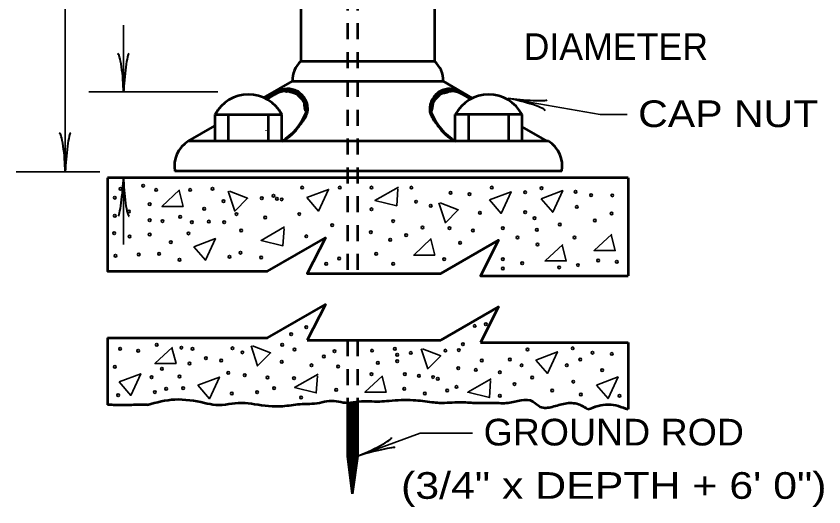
# Model space of a CAD drawing. Extents: x -608 to 72, y 36 to 476.
# Drawn here: x -462.2 to -401.7, y 238.4 to 275.1 of the extents above; entities that cross this region are included whole.
import ezdxf
from ezdxf.enums import TextEntityAlignment as Align

# ---------------------------------------------------------------- set-up
doc = ezdxf.new("R2010")
doc.units = 0
doc.header["$LTSCALE"] = 0.8
doc.linetypes.add('SHORT_DASHED', pattern=[2.7, 1.5, -1.2])
doc.layers.add('1', color=7, linetype='Continuous', lineweight=53)

msp = doc.modelspace()

# ---------------------------------------------------------------- linework, layer by layer
at = {"layer": '1'}
for p, q in [((-430.8494, 389.7532), (-430.8494, 271.7708)), ((-440.8494, 280.6042), (-440.8494, 271.7708)), ((-440.8494, 271.7708), (-430.8494, 271.7708)), ((-443.6563, 269.0234), (-441.4957, 270.2708)), ((-441.4957, 270.2708), (-430.2031, 270.2708)), ((-428.0152, 269.0077), (-430.2031, 270.2708)), ((-443.5354, 268.9779), (-442.696, 269.4626)), ((-443.4408, 268.9778), (-442.6493, 269.4348)), ((-443.4304, 268.9597), (-442.6389, 269.4167)), ((-443.415, 268.9331), (-442.6235, 269.3901)), ((-428.138, 268.9331), (-428.9295, 269.3901)), ((-428.1226, 268.9597), (-428.9141, 269.4167)), ((-428.1122, 268.9778), (-428.9037, 269.4348)), ((-428.0176, 268.9779), (-428.857, 269.4626)), ((-447.29, 265.7708), (-447.29, 267.7708)), ((-447.29, 267.7708), (-442.29, 267.7708)), ((-446.29, 265.7708), (-446.29, 267.7708)), ((-443.29, 265.7708), (-443.29, 267.7708)), ((-442.29, 265.7708), (-442.29, 267.7708)), ((-429.288, 265.7708), (-429.288, 267.7708)), ((-424.288, 267.7708), (-429.288, 267.7708)), ((-428.288, 265.7708), (-428.288, 267.7708)), ((-425.288, 265.7708), (-425.288, 267.7708)), ((-424.288, 265.7708), (-424.288, 267.7708)), ((-449.29, 265.7708), (-447.3094, 266.9143)), ((-422.4088, 265.7708), (-424.2792, 266.8507)), ((-422.3122, 265.7708), (-449.29, 265.7708)), ((-421.3122, 263.5208), (-450.29, 263.5208)), ((-416.3494, 263.0208), (-455.3494, 263.0208)), ((-416.3494, 263.0208), (-416.3494, 255.6748)), ((-455.3494, 251.0208), (-443.3494, 251.0208)), ((-455.3494, 251.0208), (-455.3494, 246.0208)), ((-440.3812, 250.8478), (-430.3812, 250.8478)), ((-427.4131, 250.6748), (-416.3494, 250.6748)), ((-416.3494, 250.6748), (-416.3494, 245.6748)), ((-437.3739, 246.1689), (-437.3739, 242.1689)), ((-437.3382, 246.1689), (-437.3382, 241.8903)), ((-437.3007, 246.1689), (-437.3007, 241.5968)), ((-437.2631, 246.1689), (-437.2631, 241.3033)), ((-437.2255, 246.1689), (-437.2255, 241.0098)), ((-437.1879, 246.1689), (-437.1879, 240.7163)), ((-437.1628, 246.1689), (-437.1628, 240.5204)), ((-437.1252, 246.1689), (-437.1252, 240.2269)), ((-437.1002, 246.1689), (-437.1002, 240.031)), ((-437.0626, 246.1689), (-437.0626, 239.7375)), ((-437.025, 246.1689), (-437.025, 239.444)), ((-436.9999, 246.1689), (-436.9999, 239.4366)), ((-436.9748, 246.1689), (-436.9748, 239.6188)), ((-436.9373, 246.1689), (-436.9373, 239.892)), ((-436.9122, 246.1689), (-436.9122, 240.0742)), ((-436.8746, 246.1689), (-436.8746, 240.3473)), ((-436.8245, 246.1689), (-436.8245, 240.7113)), ((-436.7869, 246.1689), (-436.7869, 240.9844)), ((-436.7618, 246.1689), (-436.7618, 241.1667)), ((-436.7117, 246.1689), (-436.7117, 241.5312)), ((-436.6867, 246.1689), (-436.6867, 241.7129)), ((-436.6239, 246.2541), (-436.6239, 242.1689)), ((-437.3739, 242.1689), (-437.0124, 239.3457)), ((-436.6239, 242.1689), (-437.0124, 239.3457))]:
    msp.add_line(p, q, dxfattribs=at)
at = {"layer": '1', "lineweight": 35}
for p, q in [((-458.5165, 324.3555), (-458.5165, 263.5208)), ((-454.1446, 269.4623), (-454.1446, 274.4623)), ((-447.0688, 269.4623), (-456.7412, 269.4623)), ((-455.9253, 263.4647), (-462.1882, 263.4647)), ((-454.1446, 263.0208), (-454.1446, 258.0208))]:
    msp.add_line(p, q, dxfattribs=at)
at = {"layer": '1', "linetype": 'SHORT_DASHED'}
for p, q in [((-437.3739, 276.7708), (-437.3739, 255.8478)), ((-436.6239, 276.7708), (-436.6239, 255.8478)), ((-437.3739, 250.8478), (-437.3739, 246.1689)), ((-436.6239, 250.8478), (-436.6239, 246.2541))]:
    msp.add_line(p, q, dxfattribs=at)
at = {"layer": '1', "linetype": 'SHORT_DASHED', "lineweight": 13}
for p, q in [((-437.3739, 255.8478), (-437.3739, 255.8234)), ((-436.6239, 255.8478), (-436.6239, 255.8234))]:
    msp.add_line(p, q, dxfattribs=at)
at = {"layer": '1', "lineweight": 13}
for p, q in [((-437.3739, 242.1689), (-436.6239, 242.1689)), ((-437.0124, 242.3457), (-437.0124, 239.3457)), ((-436.9989, 242.1689), (-436.9989, 242.5212))]:
    msp.add_line(p, q, dxfattribs=at)
at = {"layer": '1', "lineweight": 35}
for points in [[(-425.3201, 268.9852), (-418.4264, 267.7697), (-416.4264, 267.7697)], [(-449.9446, 262.1177), (-451.2632, 260.8869), (-449.6808, 260.8869), (-449.9885, 262.0737)], [(-446.2964, 262.0297), (-445.8129, 260.5353), (-444.8459, 261.5023), (-446.2085, 262.0297)], [(-433.5497, 262.3374), (-435.3078, 261.3265), (-433.6815, 260.9309), (-433.5936, 262.2056)], [(-430.5168, 261.1507), (-430.0333, 259.6562), (-429.0663, 260.6232), (-430.4289, 261.1507)], [(-442.0768, 259.3486), (-443.8349, 258.3377), (-442.2086, 257.9421), (-442.1207, 259.2167)], [(-431.0882, 258.4695), (-432.4068, 257.2387), (-430.8245, 257.2387), (-431.1322, 258.4255)], [(-417.5687, 258.8034), (-418.8872, 257.5727), (-417.3049, 257.5727), (-417.6126, 258.7594)], [(-421.2426, 258.0299), (-422.5612, 256.7992), (-420.9788, 256.7992), (-421.2865, 257.9859)], [(-450.472, 250.338), (-451.7906, 249.1072), (-450.2082, 249.1072), (-450.5159, 250.294)], [(-444.5821, 250.4258), (-444.0986, 248.9314), (-443.1316, 249.8984), (-444.4942, 250.4258)], [(-431.8354, 250.2061), (-431.3519, 248.7117), (-430.3849, 249.6787), (-431.7475, 250.2061)], [(-439.5714, 248.3161), (-441.3296, 247.3052), (-439.7032, 246.9096), (-439.6153, 248.1842)], [(-434.7365, 248.1842), (-436.0551, 246.9535), (-434.4727, 246.9535), (-434.7804, 248.1402)], [(-426.605, 247.9644), (-428.3632, 246.9535), (-426.7368, 246.5579), (-426.6489, 247.8326)], [(-436.6239, 242.1689), (-431.9254, 243.879), (-428.0115, 243.879)]]:
    msp.add_lwpolyline(points, dxfattribs=at)
at = {"layer": '1'}
for points in [[(-455.3494, 263.0208), (-455.3494, 256.0208), (-443.3494, 256.0208), (-439.0192, 258.5208), (-440.3812, 255.8478), (-430.3812, 255.8478), (-426.0511, 258.3478), (-427.4131, 255.6748), (-416.3494, 255.6748)], [(-430.3812, 255.8478), (-426.0511, 258.3478), (-427.4131, 255.6748)], [(-443.3494, 251.0208), (-439.0192, 253.5208), (-440.3812, 250.8478)], [(-430.3812, 250.8478), (-426.0511, 253.3478), (-427.4131, 250.6748)]]:
    msp.add_lwpolyline(points, dxfattribs=at)
at = {"layer": '1', "lineweight": 35}
for points in [[(-440.4065, 261.5462), (-439.5274, 260.5353), (-438.7802, 262.1617)], [(-422.8688, 261.4582), (-421.9897, 260.4473), (-421.2425, 262.0737)], [(-426.7368, 261.3705), (-425.8578, 260.3596), (-425.1105, 261.9859)], [(-448.8897, 257.8541), (-448.0106, 256.8432), (-447.2633, 258.4695)], [(-423.2645, 249.3709), (-422.3854, 248.36), (-421.6382, 249.9863)], [(-454.4796, 247.7226), (-453.6005, 246.7117), (-452.8533, 248.338)], [(-448.582, 247.4809), (-447.7029, 246.47), (-446.9557, 248.0963)], [(-418.7205, 247.4856), (-417.8414, 246.4747), (-417.0942, 248.101)]]:
    msp.add_lwpolyline(points, close=True, dxfattribs=at)
for centre in [(-454.3646, 262.1966), (-452.6727, 262.4382), (-451.7027, 262.1177), (-449.1533, 262.1177), (-447.4831, 262.2056), (-440.7582, 262.2934), (-437.9451, 262.2934), (-435.5716, 262.2934), (-432.5827, 262.2934), (-429.6377, 261.8978), (-426.561, 262.2934), (-424.0557, 261.9418), (-422.8249, 262.2495), (-420.2756, 261.9857), (-454.7965, 261.5375), (-443.791, 261.5023), (-442.9119, 261.6781), (-442.6482, 261.4583), (-442.2966, 261.4143), (-428.2312, 261.81), (-419.121, 261.7309), (-417.5289, 261.7132), (-452.1861, 261.0542), (-448.0985, 260.7111), (-446.648, 261.2825), (-432.2311, 261.2386), (-431.1322, 260.9309), (-420.1877, 260.843), (-454.7965, 260.184), (-453.7362, 260.5047), (-449.9006, 260.0958), (-445.681, 260.3155), (-440.9779, 260.3155), (-435.5716, 260.6672), (-427.4401, 260.4034), (-424.0557, 260.4474), (-417.5772, 260.3596), (-452.1861, 259.8456), (-451.2192, 259.7881), (-449.0215, 259.7002), (-447.7468, 259.7441), (-446.604, 259.7002), (-443.5272, 260.0518), (-438.5165, 259.4804), (-433.9452, 259.7881), (-423.3523, 260.0078), (-421.4623, 259.5243), (-418.8341, 259.8278), (-454.8448, 258.8788), (-445.3293, 259.0848), (-435.6155, 258.9529), (-431.7476, 259.3046), (-429.7257, 259.2607), (-427.9675, 259.0848), (-425.7259, 259.2607), (-423.1766, 259.1287), (-453.6847, 258.6371), (-452.1861, 258.7821), (-449.2852, 258.8651), (-440.4505, 258.6452), (-434.1651, 258.3816), (-432.9783, 258.7332), (-424.627, 258.5573), (-420.3635, 258.5573), (-450.6038, 258.2057), (-428.9345, 258.1617), (-423.1326, 258.0299), (-454.7482, 257.1868), (-453.0079, 257.2836), (-451.4829, 257.3267), (-446.2084, 257.1069), (-445.3733, 257.4146), (-443.8349, 257.0629), (-435.2199, 257.3267), (-449.9446, 256.8871), (-438.956, 256.5794), (-437.9891, 256.975), (-433.9452, 256.5794), (-430.1212, 256.9311), (-425.7259, 256.9311), (-424.2754, 256.6234), (-420.0997, 256.4915), (-418.5924, 256.8307), (-417.1905, 256.7341), (-425.7259, 256.2278), (-421.5063, 256.3157), (-440.4505, 251.8324), (-427.8357, 251.9203), (-427.0006, 252.0522), (-441.5933, 251.3049), (-451.6587, 250.5137), (-442.2526, 250.5137), (-428.7147, 250.5577), (-454.4052, 250.2103), (-453.0517, 250.0652), (-449.8127, 250.294), (-448.9776, 250.2061), (-445.9887, 250.2501), (-445.2415, 249.9424), (-441.3296, 250.1622), (-438.3407, 250.0302), (-435.5277, 250.0742), (-433.8134, 250.2061), (-432.6267, 249.8984), (-430.0334, 250.0742), (-429.0224, 250.1182), (-423.8798, 250.1622), (-420.4953, 250.2501), (-419.0198, 249.9202), (-417.5696, 249.8236), (-447.9666, 249.5028), (-446.8238, 249.327), (-442.2966, 249.2391), (-439.1318, 249.6347), (-433.6376, 249.7666), (-433.6376, 249.2831), (-427.3082, 249.327), (-425.1984, 249.4149), (-419.9239, 249.4149), (-454.792, 248.8568), (-451.2632, 248.7117), (-449.1973, 249.1072), (-440.0549, 248.9754), (-438.077, 248.8875), (-435.0881, 249.1512), (-429.0664, 248.7556), (-427.7477, 248.6238), (-424.3193, 248.9754), (-420.9349, 248.9754), (-418.2947, 248.615), (-452.0366, 248.0832), (-449.9446, 248.1402), (-446.2963, 248.404), (-445.0657, 248.2282), (-443.3514, 248.0523), (-441.3735, 248.0084), (-435.5716, 248.3161), (-433.0662, 248.3161), (-432.0113, 248.1842), (-430.9564, 248.0963), (-425.9457, 248.4479), (-423.5282, 248.0523), (-430.6047, 247.9644), (-424.8468, 247.5688), (-420.4514, 247.7447), (-451.7949, 246.9714), (-450.9555, 247.2172), (-449.6808, 247.2612), (-446.0327, 246.8656), (-444.1426, 246.9535), (-442.8679, 247.2612), (-438.2088, 247.1293), (-433.1102, 247.2172), (-431.5718, 246.8656), (-429.9015, 247.0853), (-429.1982, 247.3491), (-422.0337, 247.0853), (-419.88, 246.7777), (-454.5503, 246.7297), (-440.8461, 246.5579), (-425.9457, 246.6898), (-416.9895, 246.6814)]:
    msp.add_circle(centre, 0.1, dxfattribs=at)
at = {"layer": '1'}
for centre, radius, start, end in [((-439.6024, 270.3443), 1.8947, 131.15753, 182.22112), ((-432.0964, 270.3443), 1.8947, 357.77888, 48.84247), ((-444.79, 266.4375), 2.8333, 28.07249, 151.92751), ((-441.9941, 267.9914), 1.5294, 357.56619, 122.5437), ((-441.8732, 268.1733), 1.5294, 357.56619, 122.5437), ((-441.8732, 268.1733), 1.5294, 357.56619, 122.5437), ((-429.6798, 268.1733), 1.5294, 57.4563, 182.43381), ((-429.6798, 268.1733), 1.5294, 57.4563, 182.43381), ((-429.5589, 267.9914), 1.5294, 57.4563, 182.43381), ((-426.788, 266.4375), 2.8333, 28.07249, 151.92751), ((-442.0355, 268.3486), 1.7074, 321.26362, 351.91119), ((-429.5175, 268.3486), 1.7074, 188.08881, 218.73638), ((-444.4981, 269.4887), 4.3242, 300.70688, 338.8212), ((-427.0549, 269.4887), 4.3242, 201.1788, 239.29312), ((-443.7041, 268.7229), 3.2733, 295.59515, 327.88518), ((-475.2243, 293.4906), 43.3434, 322.29634, 322.79175), ((-396.3287, 293.4906), 43.3434, 217.20825, 217.70366), ((-427.8489, 268.7229), 3.2733, 212.11482, 244.40485), ((-445.4058, 267.8783), 2.3574, 326.68295, 327.02077), ((-448.1767, 263.9288), 2.1523, 121.14818, 190.92684), ((-423.4255, 263.9288), 2.1523, 349.07316, 58.85182)]:
    msp.add_arc(centre, radius, start, end, dxfattribs=at)
at = {"layer": '1', "lineweight": 40}
for centre, major_axis, ratio, start_param, end_param in [((-454.4209, 270.5535), (0.1562, -1.7857), 0.122415, 0.8963533, 3.1415927), ((-453.933, 270.5828), (0.1757, 1.7565), 0.07063, 6.2823074, 8.5597026), ((-424.2934, 268.5236), (-1.7315, 0.4639), 0.122415, 3.1415927, 5.386832), ((-424.1799, 268.999), (1.7603, -0.132), 0.07063, 4.006668, 6.2840632), ((-458.7928, 264.612), (0.1562, -1.7857), 0.122415, 0.8963533, 3.1415927), ((-458.3049, 264.6413), (0.1757, 1.7565), 0.07063, 6.2823074, 8.5597026), ((-454.3562, 261.9003), (-0.1757, -1.7565), 0.07063, 6.2823074, 8.5597026), ((-453.8683, 261.9296), (-0.1562, 1.7857), 0.122415, 0.8963533, 3.1415927), ((-435.693, 242.8018), (-1.6246, -0.7575), 0.122415, 0.8963533, 3.1415927), ((-435.4986, 242.3533), (1.7106, 0.4357), 0.07063, 6.2823074, 8.5597026)]:
    msp.add_ellipse(centre, major_axis=major_axis, ratio=ratio, start_param=start_param, end_param=end_param, dxfattribs=at)
at = {"layer": '1'}
for points in [[(-441.584, 266.2357), (-441.4752, 266.3445), (-441.439, 266.3928), (-441.3665, 266.4895), (-441.3061, 266.5379), (-441.2093, 266.6467), (-441.1489, 266.7192), (-440.9918, 266.9125), (-440.8952, 267.0576), (-440.8105, 267.1542), (-440.7501, 267.2267), (-440.7259, 267.2751), (-440.6534, 267.3476), (-440.6413, 267.396), (-440.6172, 267.4443), (-440.593, 267.4927), (-440.5688, 267.5652), (-440.6172, 267.4927), (-440.6776, 267.4081), (-440.7138, 267.3597), (-440.7501, 267.2751), (-440.5688, 267.6135), (-440.5084, 267.686), (-440.4722, 267.7343), (-440.4601, 267.819), (-440.5447, 267.686), (-440.5567, 267.5893), (-440.4358, 267.9157), (-440.3996, 268.0123), (-440.4117, 268.0123), (-440.4117, 268.0607), (-440.448, 268.0848), (-440.448, 268.1573), (-440.4358, 268.2057), (-440.4237, 268.2057), (-440.4237, 268.2178), (-440.4358, 268.2662), (-440.4358, 268.3387), (-440.4237, 268.3991), (-440.4601, 268.4353), (-440.4963, 268.4595), (-440.4963, 268.4837), (-440.5084, 268.532), (-440.5205, 268.5562), (-440.5205, 268.5682), (-440.5205, 268.6287), (-440.5326, 268.6771), (-440.5326, 268.6892), (-440.5447, 268.7496), (-440.5567, 268.7738), (-440.5809, 268.8342), (-440.593, 268.8342), (-440.6051, 268.8583), (-440.6293, 268.8825), (-440.7018, 268.955), (-440.7138, 269.0154), (-440.7742, 269.0517), (-440.8105, 269.1001), (-440.8105, 269.1363), (-440.8952, 269.1847), (-440.9314, 269.1968), (-441.0039, 269.2451), (-441.1127, 269.3297), (-441.1368, 269.3659), (-441.2093, 269.4022), (-441.294, 269.4384), (-441.439, 269.4626), (-441.5236, 269.4989), (-441.6807, 269.5714), (-441.9828, 269.6198), (-442.007, 269.6198), (-442.2125, 269.5835), (-442.6234, 269.4505), (-442.3454, 269.5714), (-442.2487, 269.5956), (-442.2125, 269.5956), (-442.1762, 269.5835), (-442.0916, 269.5714), (-441.9345, 269.511), (-441.8016, 269.5593), (-441.6444, 269.5231), (-441.9708, 269.5714), (-442.1521, 269.5472), (-442.0916, 269.656), (-441.9587, 269.6802), (-441.8982, 269.656), (-441.8378, 269.6439), (-441.7653, 269.656), (-441.6686, 269.6198), (-441.6082, 269.6077), (-441.5719, 269.5956), (-441.4632, 269.5835), (-441.4511, 269.5714), (-441.4148, 269.5231), (-441.3182, 269.4989), (-441.2818, 269.4868), (-441.3061, 269.4505)], [(-441.3061, 269.4505), (-441.4148, 269.4626), (-441.4148, 269.5593), (-441.4148, 269.5714), (-441.4752, 269.511), (-441.2093, 269.4626), (-441.0885, 269.4142), (-441.0039, 269.3176), (-440.9314, 269.2451), (-440.8831, 269.2209), (-440.8105, 269.1847), (-440.6655, 269.088), (-440.6655, 269.0396), (-440.6172, 268.9067), (-440.5567, 268.8462), (-440.4722, 268.6892), (-440.4237, 268.6529), (-440.3996, 268.4837), (-440.3754, 268.3749), (-440.3996, 268.2178), (-440.5326, 268.7254), (-440.6534, 268.8221), (-440.7138, 269.0396), (-440.8467, 269.1243), (-440.9797, 269.3659), (-440.7984, 269.0154), (-441.0281, 269.2692), (-441.2093, 269.3538), (-441.3423, 269.5352), (-441.0281, 269.3659), (-440.871, 269.2451), (-440.738, 268.9671), (-440.5567, 268.6045), (-440.3754, 268.1573), (-440.4117, 268.0848), (-440.593, 268.8946), (-440.593, 268.955), (-440.7018, 269.0275), (-441.0281, 269.2934), (-441.2093, 269.5231), (-441.2818, 269.5714), (-441.4511, 269.5956), (-441.6807, 269.656), (-442.1157, 269.5835), (-441.7895, 269.5714), (-441.6444, 269.5231), (-441.5478, 269.5231), (-441.5115, 269.5472), (-441.3302, 269.4747), (-441.1248, 269.3901), (-441.0643, 269.3297), (-440.9193, 269.1968), (-440.7742, 269.0396), (-440.7018, 268.9429), (-440.5688, 268.7738), (-440.3996, 268.4112), (-440.5567, 268.8583), (-440.8105, 269.2451), (-440.9918, 269.4263), (-441.1368, 269.5231), (-441.1731, 269.4989), (-440.9556, 269.2813), (-440.9072, 269.2813), (-441.0764, 269.4142), (-441.2697, 269.4022), (-442.0433, 269.6439)], [(-430.2469, 269.4505), (-430.1382, 269.4626), (-430.1382, 269.5593), (-430.1382, 269.5714), (-430.0777, 269.511), (-430.3437, 269.4626), (-430.4645, 269.4142), (-430.5491, 269.3176), (-430.6216, 269.2451), (-430.6699, 269.2209), (-430.7425, 269.1847), (-430.8875, 269.088), (-430.8875, 269.0396), (-430.9358, 268.9067), (-430.9962, 268.8462), (-431.0808, 268.6892), (-431.1293, 268.6529), (-431.1534, 268.4837), (-431.1776, 268.3749), (-431.1534, 268.2178), (-431.0204, 268.7254), (-430.8996, 268.8221), (-430.8392, 269.0396), (-430.7063, 269.1243), (-430.5732, 269.3659), (-430.7546, 269.0154), (-430.5249, 269.2692), (-430.3437, 269.3538), (-430.2107, 269.5352), (-430.5249, 269.3659), (-430.682, 269.2451), (-430.815, 268.9671), (-430.9962, 268.6045), (-431.1776, 268.1573), (-431.1413, 268.0848), (-430.96, 268.8946), (-430.96, 268.955), (-430.8512, 269.0275), (-430.5249, 269.2934), (-430.3437, 269.5231), (-430.2712, 269.5714), (-430.1019, 269.5956), (-429.8723, 269.656), (-429.4373, 269.5835), (-429.7635, 269.5714), (-429.9086, 269.5231), (-430.0052, 269.5231), (-430.0415, 269.5472), (-430.2227, 269.4747), (-430.4282, 269.3901), (-430.4887, 269.3297), (-430.6337, 269.1968), (-430.7788, 269.0396), (-430.8512, 268.9429), (-430.9842, 268.7738), (-431.1534, 268.4112), (-430.9962, 268.8583), (-430.7425, 269.2451), (-430.5612, 269.4263), (-430.4162, 269.5231), (-430.3799, 269.4989), (-430.5974, 269.2813), (-430.6457, 269.2813), (-430.4766, 269.4142), (-430.2833, 269.4022), (-429.5097, 269.6439)], [(-429.969, 266.2357), (-430.0777, 266.3445), (-430.114, 266.3928), (-430.1865, 266.4895), (-430.2469, 266.5379), (-430.3437, 266.6467), (-430.4041, 266.7192), (-430.5612, 266.9125), (-430.6578, 267.0576), (-430.7425, 267.1542), (-430.8029, 267.2267), (-430.8271, 267.2751), (-430.8996, 267.3476), (-430.9117, 267.396), (-430.9358, 267.4443), (-430.96, 267.4927), (-430.9842, 267.5652), (-430.9358, 267.4927), (-430.8754, 267.4081), (-430.8392, 267.3597), (-430.8029, 267.2751), (-430.9842, 267.6135), (-431.0446, 267.686), (-431.0808, 267.7343), (-431.0929, 267.819), (-431.0083, 267.686), (-430.9962, 267.5893), (-431.1172, 267.9157), (-431.1534, 268.0123), (-431.1413, 268.0123), (-431.1413, 268.0607), (-431.105, 268.0848), (-431.105, 268.1573), (-431.1172, 268.2057), (-431.1293, 268.2057), (-431.1293, 268.2178), (-431.1172, 268.2662), (-431.1172, 268.3387), (-431.1293, 268.3991), (-431.0929, 268.4353), (-431.0567, 268.4595), (-431.0567, 268.4837), (-431.0446, 268.532), (-431.0325, 268.5562), (-431.0325, 268.5682), (-431.0325, 268.6287), (-431.0204, 268.6771), (-431.0204, 268.6892), (-431.0083, 268.7496), (-430.9962, 268.7738), (-430.9721, 268.8342), (-430.96, 268.8342), (-430.9479, 268.8583), (-430.9237, 268.8825), (-430.8512, 268.955), (-430.8392, 269.0154), (-430.7788, 269.0517), (-430.7425, 269.1001), (-430.7425, 269.1363), (-430.6578, 269.1847), (-430.6216, 269.1968), (-430.5491, 269.2451), (-430.4403, 269.3297), (-430.4162, 269.3659), (-430.3437, 269.4022), (-430.259, 269.4384), (-430.114, 269.4626), (-430.0294, 269.4989), (-429.8723, 269.5714), (-429.5702, 269.6198), (-429.546, 269.6198), (-429.3405, 269.5835), (-428.9296, 269.4505), (-429.2076, 269.5714), (-429.3042, 269.5956), (-429.3405, 269.5956), (-429.3767, 269.5835), (-429.4614, 269.5714), (-429.6185, 269.511), (-429.7514, 269.5593), (-429.9086, 269.5231), (-429.5822, 269.5714), (-429.4009, 269.5472), (-429.4614, 269.656), (-429.5943, 269.6802), (-429.6547, 269.656), (-429.7152, 269.6439), (-429.7877, 269.656), (-429.8844, 269.6198), (-429.9448, 269.6077), (-429.9811, 269.5956), (-430.0898, 269.5835), (-430.1019, 269.5714), (-430.1382, 269.5231), (-430.2348, 269.4989), (-430.2712, 269.4868), (-430.2469, 269.4505)], [(-452.3494, 246.0208), (-450.2927, 246.418), (-448.0872, 246.1674), (-447.235, 246.017), (-445.2802, 246.1674), (-444.3277, 246.0672), (-442.2225, 245.9167), (-440.9192, 246.0672), (-439.4656, 246.1674), (-438.7138, 246.3177), (-437.3603, 246.1674), (-436.5082, 246.2677), (-434.9543, 246.2677), (-434.2526, 246.3177), (-432.4481, 246.3679), (-431.0446, 246.2175), (-430.4932, 246.1674), (-428.9392, 246.2175), (-427.8365, 246.1674), (-426.433, 246.1674), (-425.3302, 246.1674), (-423.4757, 246.2677), (-422.9242, 245.8667), (-422.022, 245.8667), (-421.0696, 246.1172), (-420.0671, 246.0672), (-419.3494, 245.6748)], [(-452.3494, 246.0208), (-453.5472, 245.9952), (-454.9007, 245.9952), (-455.3494, 246.0208)], [(-419.3494, 245.6748), (-417.8233, 246.0436), (-416.3494, 245.6748)]]:
    msp.add_spline(points, degree=3, dxfattribs=at)

# ---------------------------------------------------------------- texts
msp.add_text('DIAMETER', height=2, dxfattribs=at).set_placement((-417.2638, 271.8618), align=Align.CENTER)
at = {"layer": '1', "width": 1.15}
msp.add_text('CAP NUT', height=2, dxfattribs=at).set_placement((-415.5925, 266.8318))
at = {"layer": '1'}
for s, width, p in [('GROUND ROD', 1.05, (-417.4186, 242.9645)), ('(3/4" x DEPTH + 6\' 0")', 1.2, (-417.4187, 238.9645))]:
    msp.add_text(s, height=2, dxfattribs=dict(at, width=width)).set_placement(p, align=Align.CENTER)

doc.saveas('drawing.dxf')
